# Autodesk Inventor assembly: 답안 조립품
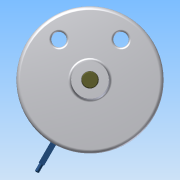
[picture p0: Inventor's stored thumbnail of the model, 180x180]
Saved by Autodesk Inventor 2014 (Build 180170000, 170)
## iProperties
Created: 2015-06
Part Number: 답안 조립품
Document SubType Name: Assembly
Designer: Administrator
Author: Administrator
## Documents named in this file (10)
- C:\Documents and Settings\Administrator\바탕 화면\450631V1019\답안 조립품.iam
- C:\Documents and Settings\Administrator\바탕 화면\450631V1019\1-본체.ipt
- C:\Documents and Settings\Administrator\바탕 화면\450631V1019\베어링62_22.ipt
- C:\Documents and Settings\Administrator\바탕 화면\450631V1019\덮개.ipt
- C:\Documents and Settings\Administrator\바탕 화면\450631V1019\축.ipt
- C:\Documents and Settings\Administrator\바탕 화면\450631V1019\멈춤링.ipt
- C:\Documents and Settings\Administrator\바탕 화면\450631V1019\슬라이더2.ipt
- C:\Documents and Settings\Administrator\바탕 화면\450631V1019\슬라이더.ipt
- C:\Documents and Settings\Administrator\바탕 화면\450631V1019\평행핀.ipt
- C:\Documents and Settings\Administrator\바탕 화면\450631V1019\M10x35.ipt
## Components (8 placed, 5 different names)
1. 1-본체:1 — 각도:1
2. KS B 2023 62/22 - 22 x 50 x 14:1
3. KS B 2023 62/22 - 22 x 50 x 14:2
4. KS B 1336 22 x 1.2:1
5. KS B 1336 22 x 1.2:2
6. KS B 1320 B B 5 x  20:1
7. KS B 1003 - 미터 M 10 x 35:1
8. KS B 1003 - 미터 M 10 x 35:2
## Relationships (1: Angle 1)
- 각도:1 [Angle]: 1-본체:1
